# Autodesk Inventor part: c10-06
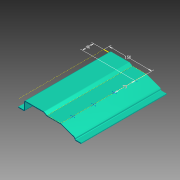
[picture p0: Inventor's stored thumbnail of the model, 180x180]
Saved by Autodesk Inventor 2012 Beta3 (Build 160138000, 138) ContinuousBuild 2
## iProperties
Created: 2011-01
Part Number: c10-06
Material: Aluminum-6061
Document SubType Name: Sheet Metal
Designer: Beta-8540w
Density: 2.71 g/cm^3
Sheet Metal Rule: Aluminum - 3.4mm
Author: Beta-8540w
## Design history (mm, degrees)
node "Contour Flange1"
  sketch "Sketch1"
    geometry: L1 (0, 0)-(20, 0); L2 (20, 0)-(20, 30); L3 (20, 30)-(90, 30); L4 (100.392, 24)-(150, 24); L5 (150, 24)-(200, 5.801); L6 (200, 5.801)-(200, 0); L7 (200, 0)-(220, 0); L8 (-200, 0)-(-200, 73.265); L9 (90, 30)-(100.392, 24); 1 further point
    constraints: 18 end point, 3 collinear, 3 parallel, 2 perpendicular, 1 coincident, 1 horizontal, 1 horizontal alignment
    dimensions: "d5" = 20 distance of L1.start L1.end; "d6" = 30 distance of L1.end L2.end; "d7" = 70 distance of L2.end L3.end; "d9" = 220 distance of L7.end point (0, 0); "d11" = 20 deg angle of L5 L4; "d12" = 200 distance from line of point (0, 0) L8; "d13" = 6 vertical distance of L3.end L4.start; "d14" = 130 distance from line of L4.end L2; "d15" = 30 deg angle of L9 L3
sketch "Sketch3" dims "d35" = 10
  geometry: L1 (48.12, 0)-(48.12, -300) reference; L2 (0, 0)-(48.12, 0) reference; L3 (0, 0)-(0, -300) reference; L4 (48.12, -300)-(0, -300) reference; L5 (-100.928, -300)-(-100.928, 0) reference; L6 (-100.928, 0)-(-82.928, 0) reference; 4 further points
  constraints: 1 vertical, 3 other
  dimensions: "d28" = 150 distance from line of point (49.072, -40) L5; "d29" = 40 distance from line of L6 point (49.072, -40); "d32" = 73 distance of point (49.072, -40) point (49.072, -113)
sketch "Cut Sketch"
  geometry: L1 (63.153, 0)-(63.153, -300) reference; L2 (0, 0)-(63.153, 0) reference; L3 (0, 0)-(0, -300) reference; L4 (63.153, -300)-(0, -300) reference; L5 (14.6, -140)-(96.274, -140); L6 (96.274, -140)-(96.274, -160); L7 (96.274, -160)-(14.6, -160); L8 (14.6, -160)-(14.6, -140); L9 (-25.4, -300)-(-25.4, 0) reference; 2 further points
  constraints: 8 end point, 2 midpoint, 2 parallel, 1 horizontal, 1 horizontal alignment, 1 perpendicular
  dimensions: "d37" = 20 distance of L7.end L5.start; "d38" = 40 distance from line of point (-25.4, -150) L8
body "Solid2"
face "Plate2" dims "d16" = 3.4 (= BendReliefWidth), "d17" = 1.7 (= BendReliefDepth), "d18" = 6.8 (= MinimumRemnant), "d19" = 2 (= BendRadius), "d20" = 300, "d21" = 2 (= BendRadius), "d22" = 3.4, "d23" = 13.6 (= CornerReliefSize), "d24" = 3.4 (= GapSize), "d25" = 2 (= JacobiRadiusSize), "SeamGap" = 0.01, "Thickness" = 3.4 (derived)
bend "Bend1" dims "d16" = 3.4 (= BendReliefWidth), "d17" = 1.7 (= BendReliefDepth), "d18" = 6.8 (= MinimumRemnant), "d19" = 2 (= BendRadius), "d21" = 2 (= BendRadius), "d22" = 3.4, "SeamGap" = 0.01, "Thickness" = 3.4 (derived)
feature "Corner1" dims "d22" = 3.4, "d23" = 13.6 (= CornerReliefSize), "d24" = 3.4 (= GapSize), "d25" = 2 (= JacobiRadiusSize)
other parameters: "BendRadius" = 2 (derived), "BendReliefWidth" = 3.4 (= Thickness), "BendReliefDepth" = 1.7 (= 0.5 x Thickness), "CornerReliefSize" = 13.6 (= 4 x Thickness), "MinimumRemnant" = 6.8 (= 2 x Thickness), "TransitionRadius" = 2 (= BendRadius), "JacobiRadiusSize" = 2 (= BendRadius), "GapSize" = 3.4 (= Thickness), "d4" = 2 (= BendRadius)
